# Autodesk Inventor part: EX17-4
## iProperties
Created: 2006-04
Part Number: EX17-4
Project: EVERGREEN VALLEY COLLEGE
Description: BUSHING
Document SubType Name: Modeling
Designer: E. MOSS
Authority: MS.TEACHER
Author: E. MOSS
Revision Number: A
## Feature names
1. Extrusion1
2. Revolution1
3. Hole1
